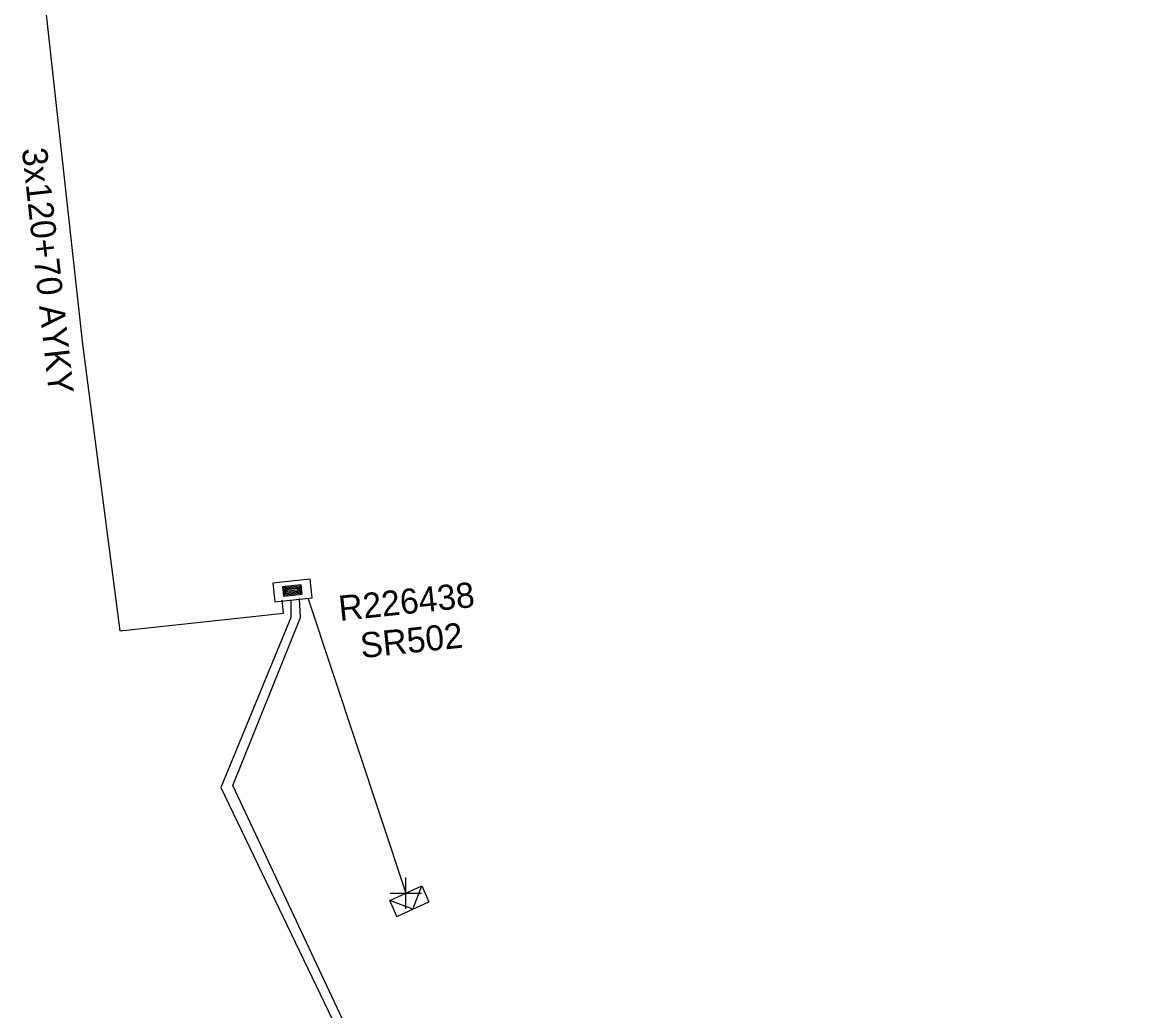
# Model space of a CAD drawing. Extents: x -544780 to -541582, y -1198995 to -1196551.
# Drawn here: x -542614.33 to -542570.37, y -1198617.52 to -1198578.18 of the extents above; entities that cross this region are included whole.
import ezdxf

# ---------------------------------------------------------------- set-up
doc = ezdxf.new("R2010")
doc.units = 0
for name, color, linetype in [('Vrstva 1', 7, 'Continuous'), ('Vrstva 28', 7, 'Continuous'), ('Vrstva 29', 7, 'Continuous'), ('Vrstva 30', 7, 'Continuous'), ('Vrstva 31', 7, 'Continuous'), ('Vrstva 34', 7, 'Continuous'), ('Vrstva 5', 7, 'Continuous'), ('Vrstva 52', 7, 'Continuous'), ('Vrstva 6', 7, 'Continuous'), ('Vrstva 8', 7, 'Continuous'), ('Vrstva 9', 7, 'Continuous')]:
    doc.layers.add(name, color=color, linetype=linetype)

# ---------------------------------------------------------------- blocks, each defined once
blk = doc.blocks.new('NN800')
at = {"layer": 'Vrstva 1'}
for points in [[(-0.442, 0.442), (0.442, -0.442)], [(-0.442, -0.442), (0.442, 0.442)]]:
    blk.add_lwpolyline(points, dxfattribs=at)
blk = doc.blocks.new('NN620')
at = {"layer": 'Vrstva 8'}
for points in [[(0.752, 0.004), (-0.748, 0.004)], [(-0.748, 0.004), (-0.748, -0.746)], [(0.752, -0.746), (0.752, 0.004)], [(0.368, -0.18), (-0.376, -0.18)], [(-0.376, -0.18), (-0.376, -0.558)], [(0.321, -0.227), (-0.329, -0.227)], [(-0.329, -0.227), (-0.329, -0.51)], [(0.274, -0.274), (-0.281, -0.274)], [(-0.281, -0.274), (-0.281, -0.463)], [(0.227, -0.321), (-0.234, -0.321)], [(-0.234, -0.321), (-0.234, -0.416)], [(-0.234, -0.416), (0.227, -0.416)], [(-0.193, -0.369), (0.185, -0.369)], [(0.227, -0.416), (0.227, -0.321)], [(0.274, -0.463), (0.274, -0.274)], [(0.321, -0.51), (0.321, -0.227)], [(0.368, -0.558), (0.368, -0.18)], [(-0.748, -0.746), (0.752, -0.746)], [(-0.376, -0.558), (0.368, -0.558)], [(-0.329, -0.51), (0.321, -0.51)], [(-0.281, -0.463), (0.274, -0.463)]]:
    blk.add_lwpolyline(points, dxfattribs=at)
blk = doc.blocks.new('NN630')
at = {"layer": 'Vrstva 9'}
for points in [[(-0.003, -0.7), (-0.703, 0)], [(-0.703, -0.7), (-0.703, 0), (0.697, 0), (0.697, -0.7)], [(-0.003, -0.7), (0.697, 0)], [(-0.703, -0.7), (0.697, -0.7)]]:
    blk.add_lwpolyline(points, dxfattribs=at)

msp = doc.modelspace()

# ---------------------------------------------------------------- linework, layer by layer
at = {"layer": 'Vrstva 5'}
for points in [[(-542598.297, -1198555.441), (-542597.765, -1198571.377), (-542612.692, -1198570.79), (-542614.114, -1198571.146), (-542611.922, -1198591), (-542610.441, -1198602.403), (-542603.926, -1198601.692), (-542603.983, -1198601.175)], [(-542603.643, -1198601.175), (-542603.643, -1198601.872), (-542606.417, -1198608.638), (-542600.333, -1198621.298), (-542602.878, -1198628.153), (-542594.994, -1198650.141), (-542582.826, -1198677.692), (-542579.598, -1198684.999)], [(-542579.113, -1198685.431), (-542570.374, -1198681.532), (-542573.106, -1198675.314), (-542571.913, -1198674.758), (-542571.988, -1198674.513), (-542573.292, -1198675.066), (-542583.97, -1198650.536), (-542582.75, -1198649.937), (-542583.039, -1198649.695), (-542584.156, -1198650.225), (-542592.91, -1198630.604), (-542591.487, -1198629.802), (-542591.606, -1198629.519), (-542593.096, -1198630.355), (-542600.174, -1198620.852), (-542605.947, -1198608.553), (-542603.251, -1198601.867), (-542603.29, -1198601.116)]]:
    msp.add_lwpolyline(points, dxfattribs=at)
at = {"layer": 'Vrstva 52'}
msp.add_lwpolyline([(-542602.964, -1198601.087), (-542599.065, -1198612.838)], dxfattribs=at)

# ---------------------------------------------------------------- block references
at = {"layer": 'Vrstva 28', "rotation": 5.963116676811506}
msp.add_blockref('NN620', (-542603.612, -1198600.426), dxfattribs=at)
at = {"layer": 'Vrstva 31', "rotation": 24.40895010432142}
msp.add_blockref('NN630', (-542599.065, -1198612.838), dxfattribs=at)
at = {"layer": 'Vrstva 34', "rotation": 44.99999995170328}
msp.add_blockref('NN800', (-542599.065, -1198612.838), dxfattribs=at)

# ---------------------------------------------------------------- texts
at = {"layer": 'Vrstva 29'}
msp.add_text('R226438', height=1, rotation=5.963, dxfattribs=at).set_placement((-542601.685, -1198602.009))
at = {"layer": 'Vrstva 30'}
msp.add_text('SR502', height=1, rotation=5.963, dxfattribs=at).set_placement((-542600.821, -1198603.487))
at = {"layer": 'Vrstva 6'}
msp.add_text('3x120+70 AYKY', height=1, rotation=276.3, dxfattribs=at).set_placement((-542614.341, -1198583.23))

doc.saveas('drawing.dxf')
